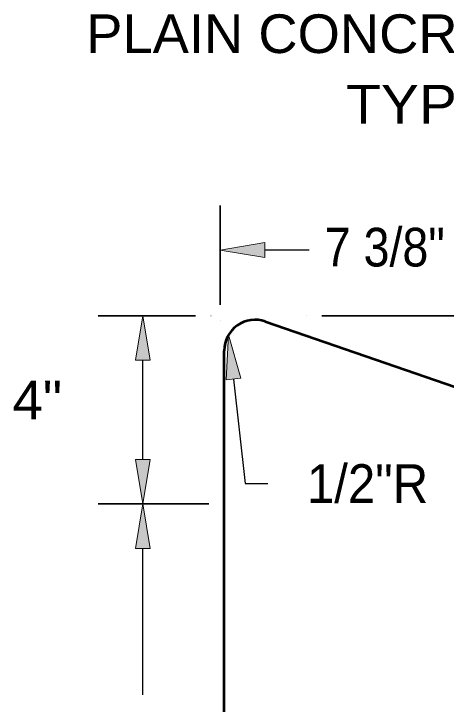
# Model space of a CAD drawing. Extents: x 36.6 to 71.9, y 0.8 to 22.8.
# Drawn here: x 55.096 to 56.841, y 8.381 to 11.17 of the extents above; entities that cross this region are included whole.
import ezdxf

# ---------------------------------------------------------------- set-up
doc = ezdxf.new("R2010")
doc.units = 0
doc.header["$LTSCALE"] = 0.062
for name, color, linetype, lineweight in [('1', 7, 'Continuous', 13), ('3', 7, 'Continuous', 25), ('8', 7, 'Continuous', 13)]:
    doc.layers.add(name, color=color, linetype=linetype, lineweight=lineweight)

msp = doc.modelspace()

# ---------------------------------------------------------------- hatches: boundary and pattern name
at = {"layer": '1'}
for points in [[(56.10833, 10.18592), (56.10833, 10.24592), (55.92833, 10.21583), (55.92833, 10.21583)], [(55.64683, 9.77025), (55.58683, 9.77025), (55.61683, 9.95025), (55.61683, 9.95025)], [(55.64683, 9.36983), (55.58683, 9.36983), (55.61683, 9.18992), (55.61683, 9.18992)], [(55.64683, 9.00992), (55.58683, 9.00992), (55.61683, 9.18992), (55.61683, 9.18992)]]:
    msp.add_hatch(color=256, dxfattribs=at).paths.add_polyline_path(points)
at = {"layer": '3'}
msp.add_hatch(color=256, dxfattribs=at).paths.add_polyline_path([(55.95242, 9.69083), (56.01208, 9.69742), (55.96242, 9.873), (55.96242, 9.873)])

# ---------------------------------------------------------------- linework, layer by layer
at = {"layer": '1', "lineweight": 35}
for p, q in [((55.92833, 9.99442), (55.92833, 10.39592)), ((55.82917, 9.95025), (55.43683, 9.95025)), ((56.33892, 9.95025), (57.61983, 9.95025)), ((55.88242, 9.18992), (55.43683, 9.18992))]:
    msp.add_line(p, q, dxfattribs=at)
at = {"layer": '1', "lineweight": 25}
for p, q in [((56.10833, 10.21592), (56.28833, 10.21592)), ((55.61683, 9.36992), (55.61683, 9.77025)), ((55.61683, 8.41817), (55.61683, 9.00992))]:
    msp.add_line(p, q, dxfattribs=at)
at = {"layer": '1', "lineweight": 53}
for p, q in [((56.11067, 9.92733), (57.12983, 9.57583)), ((55.94492, 7.16325), (55.94492, 9.80917))]:
    msp.add_line(p, q, dxfattribs=at)
at = {"layer": '1'}
msp.add_line((55.67933, 9.18992), (55.79683, 9.18992), dxfattribs=at)
for points in [[(56.10833, 10.18592), (56.10833, 10.24592), (55.92833, 10.21583), (55.92833, 10.21583)], [(55.64683, 9.77025), (55.58683, 9.77025), (55.61683, 9.95025), (55.61683, 9.95025)], [(55.64683, 9.36983), (55.58683, 9.36983), (55.61683, 9.18992), (55.61683, 9.18992)], [(55.64683, 9.00992), (55.58683, 9.00992), (55.61683, 9.18992), (55.61683, 9.18992)]]:
    msp.add_lwpolyline(points, close=True, dxfattribs=at)
at = {"layer": '1', "lineweight": 53}
msp.add_arc((56.06992, 9.80917), 0.125, 70.9727, 180, dxfattribs=at)
at = {"layer": '3', "lineweight": 13}
msp.add_lwpolyline([(55.95242, 9.69083), (56.01208, 9.69742), (55.96242, 9.873), (55.96242, 9.873)], close=True, dxfattribs=at)
at = {"layer": '3'}
msp.add_lwpolyline([(55.98225, 9.69408), (56.02908, 9.27233), (56.12067, 9.27233)], dxfattribs=at)
at = {"layer": '8'}
for p, q in [((55.61683, 9.95025), (55.61692, 9.95025)), ((55.89167, 9.95025), (55.89175, 9.95025)), ((55.92833, 9.93192), (55.92842, 9.93192)), ((56.27642, 9.95025), (56.2765, 9.95025)), ((55.61683, 9.18992), (55.61692, 9.18992)), ((55.61683, 9.18992), (55.61692, 9.18992)), ((55.94492, 9.18992), (55.945, 9.18992))]:
    msp.add_line(p, q, dxfattribs=at)

# ---------------------------------------------------------------- texts
at = {"layer": '1'}
for s, width, p in [('7 3/8"', 0.9, (56.35058, 10.14933)), ('4"', 1.05, (55.09092, 9.5315))]:
    msp.add_text(s, height=0.1562, dxfattribs=dict(at, width=width)).set_placement(p)
at = {"layer": '3'}
for s, width, p in [('PLAIN CONCRETE CURBING', 1.05, (55.388, 11.01167)), ('TYPE II ', 1.1, (56.437, 10.727)), ('1/2"R', 0.95, (56.27867, 9.19417))]:
    msp.add_text(s, height=0.1562, dxfattribs=dict(at, width=width)).set_placement(p)

doc.saveas('drawing.dxf')
